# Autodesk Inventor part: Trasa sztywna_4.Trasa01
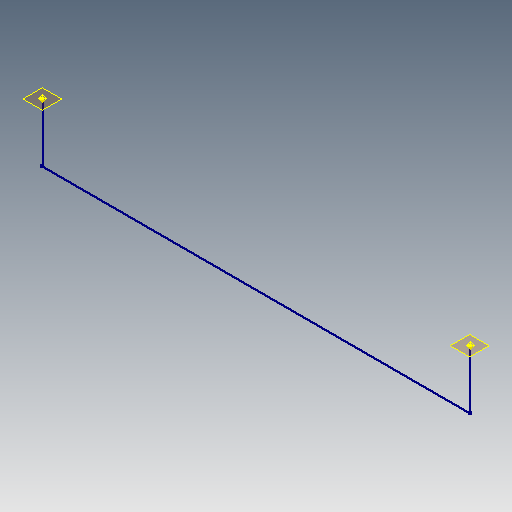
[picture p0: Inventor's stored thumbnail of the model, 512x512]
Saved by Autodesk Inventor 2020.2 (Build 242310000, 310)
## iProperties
Manager: www.cadconsulting.pl
Company: Fabian Stasiak CAD Consulting
Name: JIS G 3458/JIS B 2316 - Rury stalowe spawane i łączniki
ActiveState: True
PipeType: Rigid Pipe
Material: UnInitValue
Standard: UnInitValue
FittingMaterial: UnInitValue
FittingStandard: UnInitValue
RouteDirection90: True
RouteDirection45: True
IsFlanged: False
IsButtWelded: False
DiameterType: Nominal
Diameter: M40
Schedule: 80
OD: UnInitValue
ID: UnInitValue
Ending: UnInitValue
IntermediateSegmentsMin: 60,000 mm
IntermediateSegmentsMax: 5000,000 mm
IntermediateSegmentsInc: 1,000 mm
TerminationSegmentsMin: 60,000 mm
TerminationSegmentsMax: 5000,000 mm
TerminationSegmentsInc: 1,000 mm
RoundUpValue: UnInitValue
PipingComponentColor: As Material
PipeKey: v3#da14b0ab-0b36-4851-8d66-8c9cd0bcbe86#23
CouplingKey: v3#12b64993-10e6-4915-8315-0c0cce209ad0#8
Elbow90Key: v3#1f65ece3-c41a-48d4-8661-909ed34ade86#8
Elbow45Key: v3#28e76e79-e22c-40ab-8be2-ff545b1407c5#8
GasketKey: UnInitValue
FlangeKey: UnInitValue
_ComponentInfo: <CS><C N="Pipe" R="2.430000" IR="1.920000" PL="PL" PN="JIS G 3458 Pipe 40 A x Sch 80"><CO N="1"><FE V="0"/><FD V="1"/><ET V="Welded"/><NS V="M40"/><MA V="0.0000
Gap: UnInitValue
ShowGap: UnInitValue
MixedUnits: False
UseFlangsForCouplings: UnInitValue
IsSelfDraining: False
ElbowCustomKey: UnInitValue
_PSKETCH_SNAP: False
_PSKETCH_RSNP: False
_BASENETWORK_NOTAUTODIMENSION: False
StyleName: _Piping Style 52
Created: 2014-08
Part Number: Trasa sztywna_4.Trasa01
Material: Ogólny
Document SubType Name: Modeling
Designer: F.Stasiak
Density: 1 g/cm^3
Appearance: Domyślna
Catalog Web Link: www.expertbooks.pl
Author: F.Stasiak
Subject: Zbiór ćwiczeń. Autodesk Inventor 2020. Kurs Professional
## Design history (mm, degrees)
node "Punkt konstrukcyjny1"
node "Punkt konstrukcyjny2"
node "Płaszczyzna konstrukcyjna1"
node "Płaszczyzna konstrukcyjna2"
sketch "Szkic 3D1" dims "d0" = 150, "d1" = 150 (= d0), "d2" = 150 (derived), "d4" = 150 (derived), "d7" = 1100 (derived)
